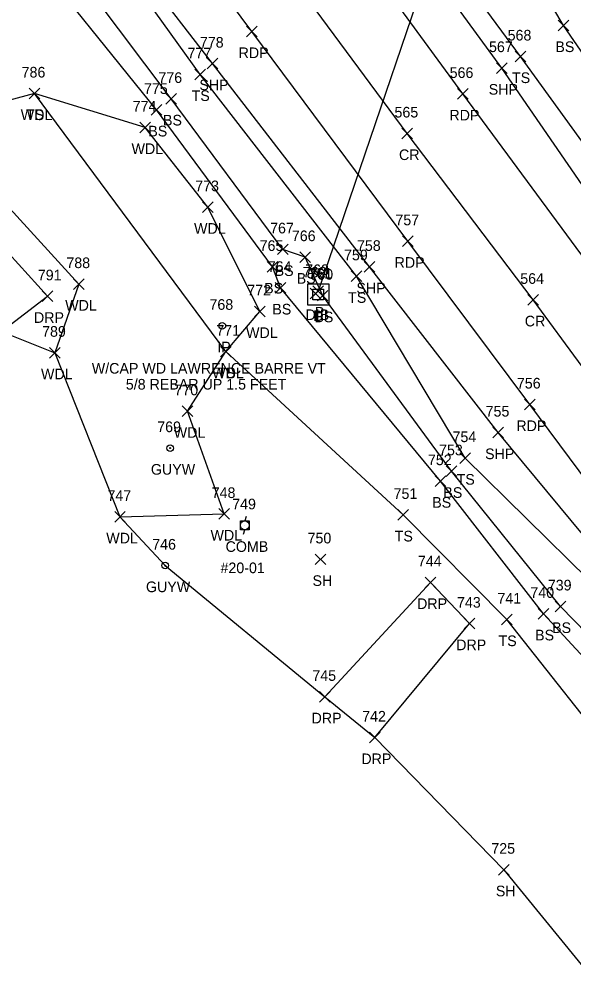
# Model space of a CAD drawing. Extents: x 1623612 to 1625808, y 621345 to 627748.
# Drawn here: x 1625042.7 to 1625147.1, y 625672.8 to 625852 of the extents above; entities that cross this region are included whole.
import ezdxf

# ---------------------------------------------------------------- set-up
doc = ezdxf.new("R2010")
doc.units = 0
for name, color, linetype in [('D_A', 7, 'Continuous'), ('D_I', 7, 'Continuous'), ('D_TIC', 7, 'Continuous'), ('DCP', 7, 'Continuous'), ('DS', 7, 'Continuous'), ('L_A', 7, 'Continuous'), ('L_I', 7, 'Continuous'), ('L_TIC', 7, 'Continuous'), ('LAWA', 7, 'Continuous'), ('LELB', 7, 'Continuous'), ('LSOGP', 7, 'Continuous'), ('M_A', 7, 'Continuous'), ('M_C', 7, 'Continuous'), ('M_I', 7, 'Continuous'), ('MPIR', 7, 'Continuous'), ('P_A', 7, 'Continuous'), ('P_I', 7, 'Continuous'), ('P_TIC', 7, 'Continuous'), ('PET', 7, 'Continuous'), ('PRC', 7, 'Continuous'), ('PSP', 7, 'Continuous'), ('R_A', 7, 'Continuous'), ('R_I', 7, 'Continuous'), ('R_TIC', 7, 'Continuous'), ('RDP', 7, 'Continuous'), ('U_A', 7, 'Continuous'), ('U_C', 7, 'Continuous'), ('U_I', 7, 'Continuous'), ('UP', 7, 'Continuous'), ('UPGW', 7, 'Continuous')]:
    doc.layers.add(name, color=color, linetype=linetype)

msp = doc.modelspace()

# ---------------------------------------------------------------- linework, layer by layer
at = {"layer": 'D_TIC'}
for points in [[(1625097.95, 625799.84), (1625099.95, 625801.84)], [(1625099.95, 625799.84), (1625097.95, 625801.84)], [(1625097.48, 625799.39), (1625099.48, 625801.39)], [(1625099.48, 625799.39), (1625097.48, 625801.39)]]:
    msp.add_lwpolyline(points, dxfattribs=at)
at = {"layer": 'DCP'}
msp.add_lwpolyline([(1625127.23, 625883.89), (1625098.95, 625800.84)], dxfattribs=at)
at = {"layer": 'DS'}
for p, q in [((1625097, 625802.19), (1625101, 625802.19)), ((1625097, 625798.19), (1625097, 625802.19)), ((1625101, 625802.19), (1625101, 625798.19)), ((1625098, 625799.19), (1625098, 625801.19)), ((1625098, 625801.19), (1625100, 625801.19)), ((1625099.01, 625800.19), (1625099.01, 625800.19)), ((1625099.01, 625800.19), (1625099.01, 625800.19)), ((1625100, 625801.19), (1625100, 625799.19)), ((1625101, 625798.19), (1625097, 625798.19)), ((1625100, 625799.19), (1625098, 625799.19))]:
    msp.add_line(p, q, dxfattribs=at)
at = {"layer": 'L_TIC'}
for points in [[(1625144.11, 625849.78), (1625146.11, 625851.78)], [(1625146.11, 625849.78), (1625144.11, 625851.78)], [(1625136, 625843.95), (1625138, 625845.95)], [(1625138, 625843.95), (1625136, 625845.95)], [(1625075.77, 625840.58), (1625077.77, 625842.58)], [(1625077.77, 625840.58), (1625075.77, 625842.58)], [(1625044.65, 625836.99), (1625046.65, 625838.99)], [(1625046.65, 625836.99), (1625044.65, 625838.99)], [(1625044.65, 625836.99), (1625046.65, 625838.99)], [(1625046.65, 625836.99), (1625044.65, 625838.99)], [(1625070.36, 625835.97), (1625072.36, 625837.97)], [(1625072.36, 625835.97), (1625070.36, 625837.97)], [(1625067.6, 625833.91), (1625069.6, 625835.91)], [(1625069.6, 625833.91), (1625067.6, 625835.91)], [(1625065.47, 625830.6), (1625067.47, 625832.6)], [(1625067.47, 625830.6), (1625065.47, 625832.6)], [(1625077.22, 625815.61), (1625079.22, 625817.61)], [(1625079.22, 625815.61), (1625077.22, 625817.61)], [(1625091.35, 625807.68), (1625093.35, 625809.68)], [(1625093.35, 625807.68), (1625091.35, 625809.68)], [(1625095.5, 625806.22), (1625097.5, 625808.22)], [(1625097.5, 625806.22), (1625095.5, 625808.22)], [(1625089.38, 625804.38), (1625091.38, 625806.38)], [(1625091.38, 625804.38), (1625089.38, 625806.38)], [(1625105.2, 625802.62), (1625107.2, 625804.62)], [(1625107.2, 625802.62), (1625105.2, 625804.62)], [(1625053, 625801.15), (1625055, 625803.15)], [(1625055, 625801.15), (1625053, 625803.15)], [(1625090.91, 625800.43), (1625092.91, 625802.43)], [(1625092.91, 625800.43), (1625090.91, 625802.43)], [(1625098.82, 625798.97), (1625100.82, 625800.97)], [(1625100.82, 625798.97), (1625098.82, 625800.97)], [(1625087, 625796.01), (1625089, 625798.01)], [(1625089, 625796.01), (1625087, 625798.01)], [(1625048.45, 625788.24), (1625050.45, 625790.24)], [(1625050.45, 625788.24), (1625048.45, 625790.24)], [(1625080.63, 625788.44), (1625082.63, 625790.44)], [(1625082.63, 625788.44), (1625080.63, 625790.44)], [(1625080.63, 625788.44), (1625082.63, 625790.44)], [(1625082.63, 625788.44), (1625080.63, 625790.44)], [(1625073.4, 625777.24), (1625075.4, 625779.24)], [(1625075.4, 625777.24), (1625073.4, 625779.24)], [(1625125.59, 625768.43), (1625127.59, 625770.43)], [(1625127.59, 625768.43), (1625125.59, 625770.43)], [(1625123.06, 625765.95), (1625125.06, 625767.95)], [(1625125.06, 625765.95), (1625123.06, 625767.95)], [(1625120.97, 625764.1), (1625122.97, 625766.1)], [(1625122.97, 625764.1), (1625120.97, 625766.1)], [(1625060.72, 625757.38), (1625062.72, 625759.38)], [(1625062.72, 625757.38), (1625060.72, 625759.38)], [(1625080.33, 625757.92), (1625082.33, 625759.92)], [(1625082.33, 625757.92), (1625080.33, 625759.92)], [(1625113.95, 625757.75), (1625115.95, 625759.75)], [(1625115.95, 625757.75), (1625113.95, 625759.75)], [(1625098.42, 625749.39), (1625100.42, 625751.39)], [(1625100.42, 625749.39), (1625098.42, 625751.39)], [(1625143.51, 625740.54), (1625145.51, 625742.54)], [(1625145.51, 625740.54), (1625143.51, 625742.54)], [(1625140.31, 625739.15), (1625142.31, 625741.15)], [(1625142.31, 625739.15), (1625140.31, 625741.15)], [(1625133.46, 625738.07), (1625135.46, 625740.07)], [(1625135.46, 625738.07), (1625133.46, 625740.07)], [(1625132.89, 625691.03), (1625134.89, 625693.03)], [(1625134.89, 625691.03), (1625132.89, 625693.03)]]:
    msp.add_lwpolyline(points, dxfattribs=at)
at = {"layer": 'LAWA'}
msp.add_lwpolyline([(1625061.72, 625758.38), (1625081.33, 625758.92), (1625074.4, 625778.24), (1625081.63, 625789.44), (1625088, 625797.01), (1625078.22, 625816.61), (1625066.47, 625831.6), (1625045.65, 625837.99), (1625026.02, 625832.74), (1625054, 625802.15), (1625049.45, 625789.24)], dxfattribs=at)
at = {"layer": 'LELB'}
for points in [[(1625193.27, 625769.69), (1625186.11, 625778.21), (1625160.35, 625812.67), (1625137, 625844.95), (1625111.86, 625879.08), (1625088.56, 625911.82), (1625060.85, 625950.33), (1625047.71, 625975.33), (1625052.42, 625981.17), (1625063.04, 625985.99), (1625075.2, 625984.93)], [(1625202.25, 625783.14), (1625199.96, 625782.54), (1625187.42, 625789.56), (1625167.73, 625817.91), (1625145.11, 625850.78), (1625123.78, 625887.07), (1625100.8, 625920.19), (1625070.14, 625955.57), (1625055.43, 625973.35)], [(1625168.33, 625721.63), (1625149.76, 625746.59), (1625126.59, 625769.43), (1625106.2, 625803.62), (1625076.77, 625841.58), (1625052.58, 625875.28), (1625029.12, 625904.57), (1625004.47, 625931.93), (1624997.4, 625934.09), (1624989.72, 625933.4), (1624984.53, 625931.05), (1624958.97, 625909.04), (1624940.42, 625892.52)], [(1625164.57, 625720.98), (1625144.51, 625741.54), (1625124.06, 625766.95), (1625099.82, 625799.97), (1625096.5, 625807.22), (1625092.35, 625808.68), (1625071.36, 625836.97), (1625046.4, 625870.19), (1625023.79, 625899.18), (1625007.76, 625918.06), (1624995.06, 625928.3), (1624989.75, 625931.76), (1624987.2, 625929.74), (1624981.22, 625924.84), (1624974.29, 625920.07), (1624955.76, 625903.44), (1624945.54, 625893.78)], [(1625164.57, 625720.98), (1625161.19, 625718.67), (1625141.31, 625740.15), (1625121.97, 625765.1), (1625091.91, 625801.43), (1625090.38, 625805.38), (1625068.6, 625834.91), (1625042.56, 625867.17), (1625020.24, 625896.3), (1625004.95, 625914.55), (1624991.81, 625925.45), (1624982.31, 625924.1), (1624975.67, 625918.28), (1624956.23, 625901.03), (1624946.56, 625892.17)], [(1625168.33, 625721.63), (1625167.65, 625717.32), (1625156.95, 625710.6), (1625134.46, 625739.07), (1625114.95, 625758.75), (1625081.63, 625789.44), (1625045.65, 625837.99)]]:
    msp.add_lwpolyline(points, dxfattribs=at)
at = {"layer": 'LSOGP'}
msp.add_lwpolyline([(1624890.51, 625970.57), (1624908.29, 625937.99), (1624911.39, 625931.54), (1624922.62, 625919.78), (1624924.08, 625917.73), (1624933.96, 625907.07), (1624939.04, 625894.21), (1624940.42, 625892.52), (1624946.29, 625884.49), (1624949.46, 625880.41), (1624962.2, 625864.8), (1624970.73, 625857.12), (1625005.75, 625827.81), (1625039.43, 625793.26), (1625049.45, 625789.24), (1625061.72, 625758.38), (1625070.2, 625749.22), (1625100.25, 625724.54), (1625109.6, 625716.88), (1625133.89, 625692.03), (1625155.14, 625666)], dxfattribs=at)
at = {"layer": 'MPIR'}
for radius in [0.625, 0.0833]:
    msp.add_circle((1625080.95, 625794.31), radius, dxfattribs=at)
at = {"layer": 'P_TIC'}
for points in [[(1625085.53, 625848.64), (1625087.53, 625850.64)], [(1625087.53, 625848.64), (1625085.53, 625850.64)], [(1625078.11, 625842.61), (1625080.11, 625844.61)], [(1625080.11, 625842.61), (1625078.11, 625844.61)], [(1625132.5, 625841.77), (1625134.5, 625843.77)], [(1625134.5, 625841.77), (1625132.5, 625843.77)], [(1625125.15, 625836.91), (1625127.15, 625838.91)], [(1625127.15, 625836.91), (1625125.15, 625838.91)], [(1625114.73, 625829.47), (1625116.73, 625831.47)], [(1625116.73, 625829.47), (1625114.73, 625831.47)], [(1625114.85, 625809.21), (1625116.85, 625811.21)], [(1625116.85, 625809.21), (1625114.85, 625811.21)], [(1625107.64, 625804.39), (1625109.64, 625806.39)], [(1625109.64, 625804.39), (1625107.64, 625806.39)], [(1625138.37, 625798.19), (1625140.37, 625800.19)], [(1625140.37, 625798.19), (1625138.37, 625800.19)], [(1625137.75, 625778.51), (1625139.75, 625780.51)], [(1625139.75, 625778.51), (1625137.75, 625780.51)], [(1625131.81, 625773.23), (1625133.81, 625775.23)], [(1625133.81, 625773.23), (1625131.81, 625775.23)]]:
    msp.add_lwpolyline(points, dxfattribs=at)
at = {"layer": 'PET'}
for points in [[(1625223.77, 625705.98), (1625197.34, 625741.92), (1625177.42, 625768.95), (1625149.4, 625806.39), (1625126.15, 625837.91), (1625100.61, 625872.87), (1625078.39, 625904.23), (1625050.83, 625943.53), (1625026.61, 625979.68), (1625001.56, 626017.54), (1624975.55, 626056.33), (1624956.14, 626085.5), (1624926, 626129.47), (1624907.51, 626155.92), (1624881.56, 626192.36), (1624859.36, 626223.09), (1624835.81, 626254.93), (1624815.05, 626283.37), (1624795.69, 626312.41), (1624789.97, 626324.03), (1624786.26, 626337.17), (1624785.07, 626353.04), (1624787.66, 626371.25), (1624792.4, 626386.87)], [(1625203.84, 625692.06), (1625178.56, 625725.93), (1625159.1, 625752.13), (1625138.75, 625779.51), (1625115.85, 625810.21), (1625086.53, 625849.64), (1625062.28, 625882.29), (1625040.04, 625911.41), (1625011.87, 625940.67), (1624992.38, 625961.15), (1624963.94, 625995.04), (1624945.44, 626018.77), (1624918.36, 626053.4), (1624893.3, 626084.98), (1624858.44, 626129.32)]]:
    msp.add_lwpolyline(points, dxfattribs=at)
at = {"layer": 'PRC'}
msp.add_lwpolyline([(1625213.58, 625698.73), (1625187.25, 625734.61), (1625167.02, 625761.6), (1625139.37, 625799.19), (1625115.73, 625830.47), (1625089.34, 625866.2), (1625066.75, 625896.39), (1625037.44, 625935.12), (1625012.58, 625969.02), (1624983.87, 626006.31), (1624957.44, 626043.36), (1624936.34, 626072.24), (1624905.82, 626116.16), (1624884.45, 626141.57), (1624859.03, 626175.57)], dxfattribs=at)
at = {"layer": 'PSP'}
for points in [[(1625197.89, 625687.83), (1625193.57, 625693.81), (1625173.65, 625722.07), (1625153.52, 625749.21), (1625132.81, 625774.23), (1625108.64, 625805.39), (1625079.11, 625843.61), (1625053.93, 625876.29), (1625030.83, 625905.94), (1625006.8, 625934.64), (1624989.43, 625958.35), (1624960.91, 625992.11), (1624942.41, 626016.35), (1624915.38, 626050.56), (1624890.43, 626082.85), (1624855.5, 626126.62)], [(1625229.23, 625710.23), (1625203.41, 625745.51), (1625190.36, 625762.87), (1625182.48, 625773.25), (1625155.83, 625810.32), (1625133.5, 625842.77), (1625108.2, 625877.47), (1625085.19, 625909.84), (1625057.82, 625948.13), (1625042.32, 625969.75), (1625027.64, 625990.04), (1625006.51, 626020.44), (1624979.39, 626058.85), (1624958.59, 626087.14), (1624930.55, 626127.2)]]:
    msp.add_lwpolyline(points, dxfattribs=at)
at = {"layer": 'R_TIC'}
for points in [[(1625047.07, 625798.85), (1625049.07, 625800.85)], [(1625049.07, 625798.85), (1625047.07, 625800.85)], [(1625119.07, 625745.05), (1625121.07, 625747.05)], [(1625121.07, 625745.05), (1625119.07, 625747.05)], [(1625126.43, 625737.3), (1625128.43, 625739.3)], [(1625128.43, 625737.3), (1625126.43, 625739.3)], [(1625099.25, 625723.54), (1625101.25, 625725.54)], [(1625101.25, 625723.54), (1625099.25, 625725.54)], [(1625108.6, 625715.88), (1625110.6, 625717.88)], [(1625110.6, 625715.88), (1625108.6, 625717.88)]]:
    msp.add_lwpolyline(points, dxfattribs=at)
at = {"layer": 'RDP'}
for points in [[(1625039.43, 625793.26), (1625048.07, 625799.85), (1625028.05, 625821.91), (1625014.45, 625834.98), (1624993.43, 625850.75), (1624981.59, 625860.99), (1624974.37, 625860.08), (1624970.73, 625857.12)], [(1625109.6, 625716.88), (1625127.43, 625738.3), (1625120.07, 625746.05), (1625100.25, 625724.54)]]:
    msp.add_lwpolyline(points, dxfattribs=at)
at = {"layer": 'UP'}
for p, q in [((1625084.35, 625755.95), (1625084.35, 625757.62)), ((1625084.35, 625757.62), (1625086.01, 625757.62)), ((1625085.43, 625758.45), (1625085.18, 625757.62)), ((1625085.18, 625756.79), (1625085.18, 625756.79)), ((1625086.01, 625757.62), (1625086.01, 625755.95)), ((1625086.01, 625755.95), (1625084.35, 625755.95)), ((1625084.93, 625755.12), (1625085.18, 625755.95))]:
    msp.add_line(p, q, dxfattribs=at)
msp.add_circle((1625085.18, 625756.79), 0.833, dxfattribs=at)
at = {"layer": 'UPGW'}
for centre, radius in [((1625071.14, 625771.31), 0.625), ((1625071.14, 625771.31), 0.0833), ((1625070.2, 625749.22), 0.625), ((1625070.2, 625749.22), 0.0833)]:
    msp.add_circle(centre, radius, dxfattribs=at)

# ---------------------------------------------------------------- texts
at = {"layer": 'D_A'}
for s, p in [('DIB', (1625096.58, 625795.39)), ('DI', (1625098.06, 625795.19)), ('P', (1625098.32, 625795.84))]:
    msp.add_text(s, height=2, dxfattribs=at).set_placement(p)
at = {"layer": 'D_I'}
for s, p in [('762', (1625096.07, 625803.39)), ('763', (1625096.54, 625803.84)), ('761', (1625097.16, 625803.19))]:
    msp.add_text(s, height=2, dxfattribs=at).set_placement(p)
at = {"layer": 'L_A'}
for s, p in [('BS', (1625143.56, 625845.78)), ('TS', (1625135.41, 625839.95)), ('TS', (1625075.18, 625836.58)), ('WDL', (1625043.06, 625832.99)), ('TS', (1625044.06, 625832.99)), ('BS', (1625069.8, 625831.97)), ('BS', (1625067.04, 625829.91)), ('WDL', (1625063.89, 625826.6)), ('WDL', (1625075.64, 625811.61)), ('BS', (1625090.79, 625803.68)), ('BS', (1625094.94, 625802.22)), ('BS', (1625088.82, 625800.38)), ('TS', (1625104.6, 625798.62)), ('WDL', (1625051.42, 625797.15)), ('BS', (1625090.35, 625796.43)), ('BS', (1625098.26, 625794.97)), ('WDL', (1625085.42, 625792.01)), ('WDL', (1625046.87, 625784.24)), ('WDL', (1625079.05, 625784.44)), ('TS', (1625080.04, 625784.44)), ('WDL', (1625071.82, 625773.24)), ('TS', (1625125, 625764.43)), ('BS', (1625122.5, 625761.95)), ('BS', (1625120.41, 625760.1)), ('WDL', (1625059.14, 625753.38)), ('WDL', (1625078.74, 625753.92)), ('TS', (1625113.36, 625753.75)), ('SH', (1625097.91, 625745.39)), ('BS', (1625139.75, 625735.15)), ('BS', (1625142.95, 625736.54)), ('TS', (1625132.87, 625734.07)), ('SH', (1625132.37, 625687.03))]:
    msp.add_text(s, height=2, dxfattribs=at).set_placement(p)
at = {"layer": 'L_I'}
for s, p in [('568', (1625134.59, 625847.95)), ('777', (1625074.41, 625844.58)), ('786', (1625043.23, 625840.99)), ('786', (1625043.23, 625840.99)), ('776', (1625068.94, 625839.97)), ('775', (1625066.23, 625837.91)), ('774', (1625064.11, 625834.6)), ('773', (1625075.86, 625819.61)), ('767', (1625089.94, 625811.68)), ('766', (1625094.03, 625810.22)), ('765', (1625087.97, 625808.38)), ('759', (1625103.83, 625806.62)), ('788', (1625051.64, 625805.15)), ('764', (1625089.5, 625804.43)), ('760', (1625097.32, 625802.97)), ('772', (1625085.64, 625800.01)), ('771', (1625079.83, 625792.44)), ('771', (1625079.83, 625792.44)), ('789', (1625047.08, 625792.24)), ('770', (1625071.95, 625781.24)), ('754', (1625124.23, 625772.43)), ('753', (1625121.7, 625769.95)), ('752', (1625119.61, 625768.1)), ('748', (1625078.96, 625761.92)), ('747', (1625059.36, 625761.38)), ('751', (1625113.15, 625761.75)), ('750', (1625096.98, 625753.39)), ('739', (1625142.14, 625744.54)), ('740', (1625138.86, 625743.15)), ('741', (1625132.67, 625742.07)), ('725', (1625131.52, 625695.03))]:
    msp.add_text(s, height=2, dxfattribs=at).set_placement(p)
at = {"layer": 'M_A'}
msp.add_text('IP', height=2, dxfattribs=at).set_placement((1625080, 625789.31))
at = {"layer": 'M_C'}
for s, p in [('W/CAP WD LAWRENCE BARRE VT', (1625056.42, 625785.31)), ('5/8 REBAR UP 1.5 FEET', (1625062.82, 625782.31))]:
    msp.add_text(s, height=2, dxfattribs=at).set_placement(p)
at = {"layer": 'M_I'}
msp.add_text('768', height=2, dxfattribs=at).set_placement((1625078.54, 625797.31))
at = {"layer": 'P_A'}
for s, p in [('RDP', (1625084.02, 625844.64)), ('SHP', (1625076.64, 625838.61)), ('SHP', (1625131.03, 625837.77)), ('RDP', (1625123.64, 625832.91)), ('CR', (1625114.17, 625825.47)), ('RDP', (1625113.34, 625805.21)), ('SHP', (1625106.17, 625800.39)), ('CR', (1625137.81, 625794.19)), ('RDP', (1625136.23, 625774.51)), ('SHP', (1625130.35, 625769.23))]:
    msp.add_text(s, height=2, dxfattribs=at).set_placement(p)
at = {"layer": 'P_I'}
for s, p in [('778', (1625076.74, 625846.61)), ('567', (1625131.09, 625845.77)), ('566', (1625123.69, 625840.91)), ('565', (1625113.32, 625833.47)), ('757', (1625113.49, 625813.21)), ('758', (1625106.27, 625808.39)), ('564', (1625136.96, 625802.19)), ('756', (1625136.33, 625782.51)), ('755', (1625130.45, 625777.23))]:
    msp.add_text(s, height=2, dxfattribs=at).set_placement(p)
at = {"layer": 'R_A'}
for p in [(1625045.55, 625794.85), (1625117.56, 625741.05), (1625124.92, 625733.3), (1625097.73, 625719.54), (1625107.09, 625711.88)]:
    msp.add_text('DRP', height=2, dxfattribs=at).set_placement(p)
at = {"layer": 'R_I'}
for s, p in [('791', (1625046.27, 625802.85)), ('744', (1625117.71, 625749.05)), ('743', (1625125.07, 625741.3)), ('745', (1625097.88, 625727.54)), ('742', (1625107.24, 625719.88))]:
    msp.add_text(s, height=2, dxfattribs=at).set_placement(p)
at = {"layer": 'U_A'}
for s, p in [('GUYW', (1625067.53, 625766.31)), ('COMB', (1625081.57, 625751.79)), ('GUYW', (1625066.6, 625744.22))]:
    msp.add_text(s, height=2, dxfattribs=at).set_placement(p)
at = {"layer": 'U_C'}
msp.add_text('#20-01', height=2, dxfattribs=at).set_placement((1625080.61, 625747.79))
at = {"layer": 'U_I'}
for s, p in [('769', (1625068.72, 625774.31)), ('749', (1625082.81, 625759.79)), ('746', (1625067.78, 625752.22))]:
    msp.add_text(s, height=2, dxfattribs=at).set_placement(p)

doc.saveas('drawing.dxf')
